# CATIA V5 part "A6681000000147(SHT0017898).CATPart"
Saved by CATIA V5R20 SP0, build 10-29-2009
Part number: A668100000147(SHT0017898)
Source: Unknown
Bounding box of the stored display mesh (mm): x -453 to 31, y 582 to 876, z 0.9 to 38.4
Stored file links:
  F:\福田A6\17-新能源车\数据\变更后数据\A668100000147（SHT0017898）-副司机座椅底支架总成\A668100000147（SHT0017898）-副司机座椅底支架总成\A6681000000007(SHT0016629).CATPart
  F:\福田A6\17-新能源车\数据\变更后数据\A668100000147（SHT0017898）-副司机座椅底支架总成\A668100000147（SHT0017898）-副司机座椅底支架总成\SHT0017898-20250326.CATPart

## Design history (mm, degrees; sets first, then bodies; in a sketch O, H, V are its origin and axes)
Body1 "1" (main body)
Body2 "Q37108-焊接方螺母"
  Solid1: solid without history
Body3 "Q37108-焊接方螺母"
  Solid2: solid without history
Body4 "Q37108-焊接方螺母"
  Solid3: solid without history
Body5 "Q37108-焊接方螺母"
  Solid4: solid without history
Body6 "Q37108-焊接方螺母"
  Solid5: solid without history
Body7 "Q37108-焊接方螺母"
  Solid6: solid without history
Body8 "SHT0017894-副驾底支架上板"
  Solid7: solid without history
Body9 "SHT0017895-副驾底支架左下板"
  Solid8: solid without history
Body10 "SHT0017896-副驾底支架右下板"
  Solid9: solid without history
